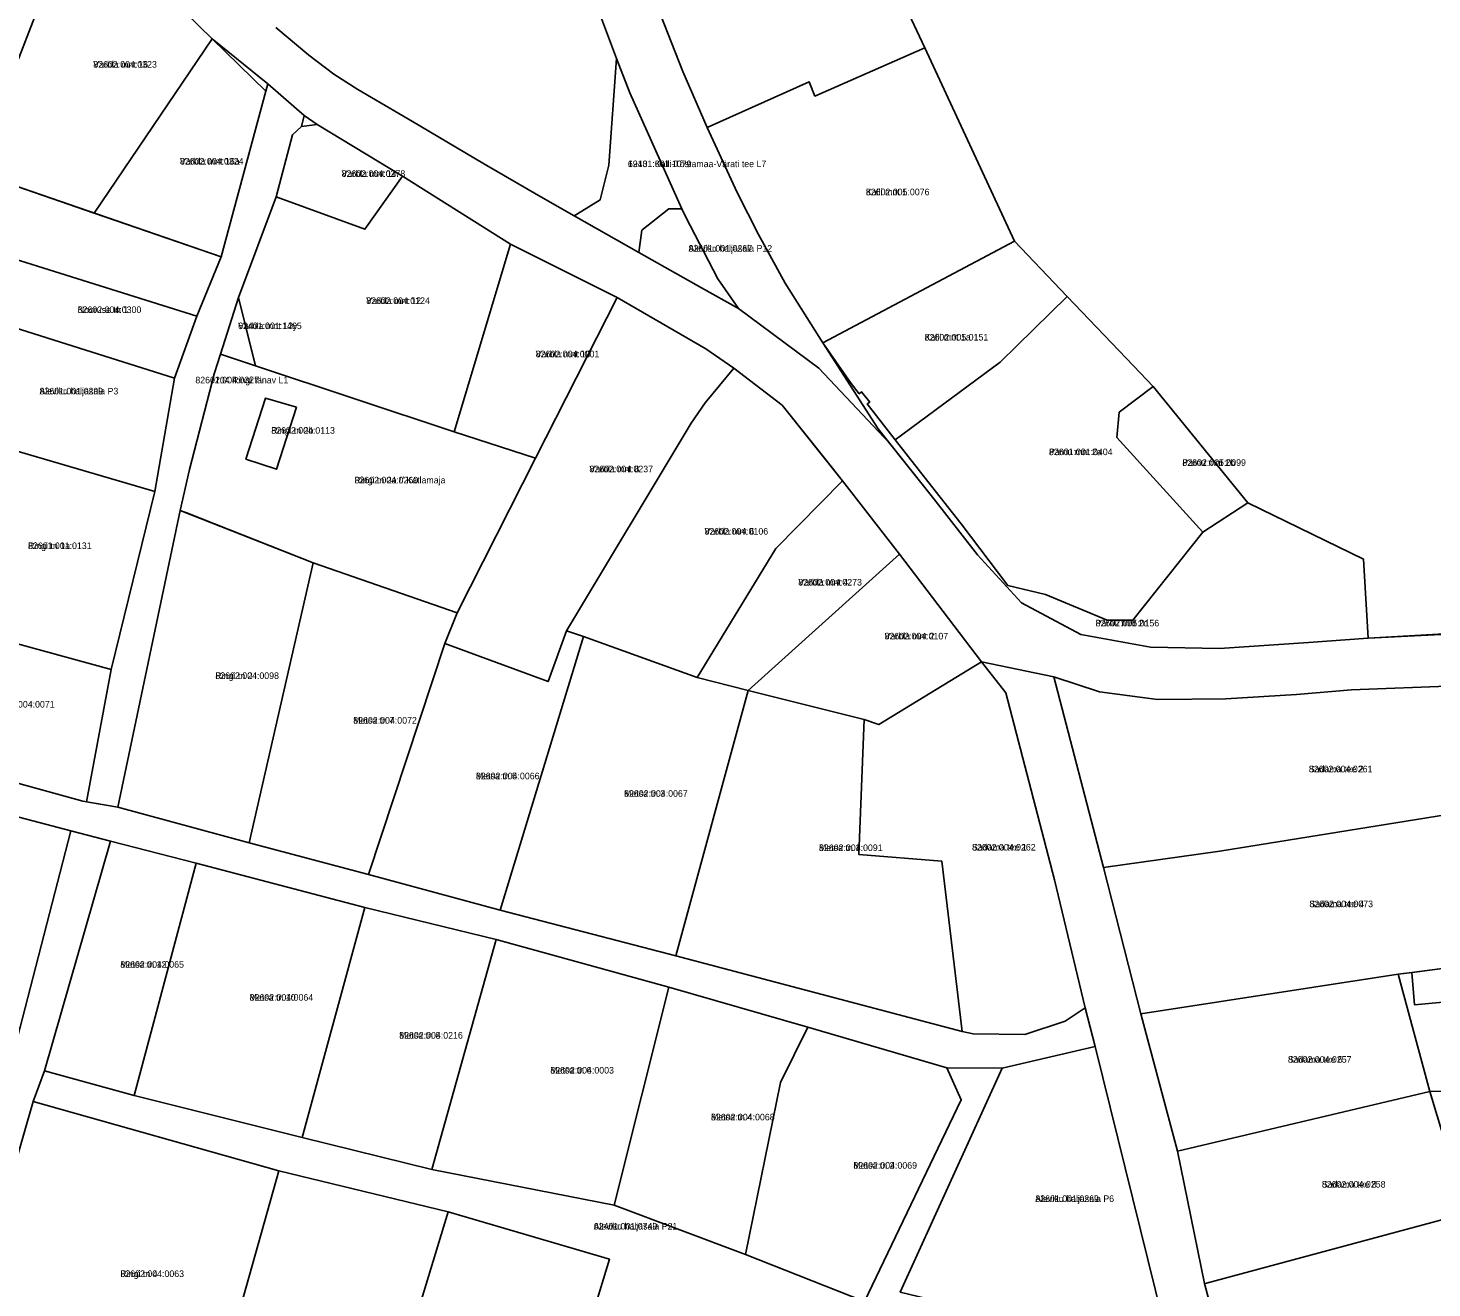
# Model space of a CAD drawing. Extents: x 491424 to 557740, y 6448618 to 6487207.
# Drawn here: x 499448.5 to 499768.6, y 6465851.5 to 6466138.8 of the extents above; entities that cross this region are included whole.
import ezdxf

# ---------------------------------------------------------------- set-up
doc = ezdxf.new("R2010")
doc.units = 0
for name, color, linetype in [('L_AADRESS', 7, 'Continuous'), ('PIIR', 7, 'Continuous'), ('TUNNUS', 7, 'Continuous')]:
    doc.layers.add(name, color=color, linetype=linetype)

msp = doc.modelspace()

# ---------------------------------------------------------------- linework, layer by layer
at = {"layer": 'PIIR'}
for points in [[(499579.95, 6466182.01), (499626.61, 6466190.35), (499652.93, 6466134.29), (499627.91, 6466123.27), (499626.61, 6466126.48), (499603.34, 6466116.11), (499597.78, 6466128.89), (499589.28, 6466150.63)], [(499407.26, 6466122.72), (499409.08, 6466128.35), (499426.33, 6466181.69), (499459.72, 6466166.41), (499436.29, 6466106), (499415.74, 6466117.84)], [(499490.51, 6466136.31), (499463.6, 6466096.59), (499436.29, 6466106), (499459.72, 6466166.41)], [(499502.73, 6466124.42), (499492.53, 6466086.63), (499463.6, 6466096.59), (499490.51, 6466136.31)], [(499603.34, 6466116.11), (499626.61, 6466126.48), (499627.91, 6466123.27), (499652.93, 6466134.29), (499673.44, 6466090.17), (499629.73, 6466067.03), (499621.13, 6466080.58), (499615.01, 6466091.72), (499610.15, 6466101.32)], [(499572.99, 6466095.95), (499573.8, 6466096.45), (499578.94, 6466099.6), (499580.89, 6466107.48), (499582.65, 6466131.85), (499585.72, 6466124.03), (499597.55, 6466097.53), (499594.57, 6466097.57), (499588.42, 6466092.68), (499587.73, 6466087.57)], [(499503.18, 6466126.09), (499511.5, 6466118.84), (499510.84, 6466116.31), (499508.83, 6466114.42), (499505.11, 6466100.26), (499496.47, 6466077.34), (499492.42, 6466064.45), (499491.07, 6466060.19), (499485.3, 6466038.14), (499483.2, 6466028.81), (499468.97, 6465961.11), (499461.84, 6465962.37), (499467.5, 6465992.52), (499477.45, 6466033.12), (499481.92, 6466058.94), (499487.01, 6466073.12), (499492.53, 6466086.63), (499502.73, 6466124.42)], [(499278.28, 6466026.77), (499288.17, 6466044.36), (499295.64, 6466056.89), (499304.55, 6466072.74), (499329.52, 6466088.43), (499340.09, 6466107.25), (499372.79, 6466096.28), (499404.99, 6466085.73), (499411.81, 6466106.27), (499415.74, 6466117.84), (499436.29, 6466106), (499492.53, 6466086.63), (499487.01, 6466073.12), (499437.57, 6466088.58), (499427.21, 6466088.67), (499423.61, 6466077.37), (499416.95, 6466056.51), (499375.43, 6466069.39), (499370.81, 6466055.84), (499368.18, 6466048.29), (499317.32, 6466066.39), (499311.41, 6466057.28), (499308.22, 6466047.25), (499283.94, 6466022.3)], [(499533.86, 6466105.03), (499525.34, 6466092.9), (499505.11, 6466100.26), (499508.83, 6466114.42), (499510.84, 6466116.31), (499514.47, 6466116.8)], [(499558.49, 6466089.53), (499545.7, 6466046.7), (499500.41, 6466061.78), (499496.47, 6466077.34), (499505.11, 6466100.26), (499525.34, 6466092.9), (499533.86, 6466105.03)], [(499610.46, 6466074.84), (499602.08, 6466079.52), (499587.73, 6466087.57), (499588.42, 6466092.68), (499594.57, 6466097.57), (499597.55, 6466097.53), (499598.38, 6466095.78), (499605.74, 6466081.59)], [(499487.01, 6466073.12), (499481.92, 6466058.94), (499423.61, 6466077.37), (499427.21, 6466088.67), (499437.57, 6466088.58)], [(499558.49, 6466089.53), (499582.81, 6466077.37), (499564.22, 6466040.7), (499545.7, 6466046.7)], [(499673.44, 6466090.17), (499685.4, 6466077.57), (499670.1, 6466062.57), (499646.22, 6466044.9), (499639.85, 6466053.07), (499640.39, 6466053.49), (499638.56, 6466055.82), (499638.01, 6466055.4), (499636.14, 6466057.76), (499629.73, 6466067.03)], [(499416.95, 6466056.51), (499423.61, 6466077.37), (499481.92, 6466058.94), (499477.45, 6466033.12), (499428.37, 6466047.47), (499429.97, 6466052.47)], [(499500.41, 6466061.78), (499492.42, 6466064.45), (499496.47, 6466077.34), (499499.81, 6466064.14)], [(499567.06, 6465989.79), (499543.54, 6465998.45), (499546.36, 6466005.46), (499564.22, 6466040.7), (499582.81, 6466077.37), (499603.04, 6466065.64), (499609.46, 6466061.24), (499602.9, 6466053.32), (499599.67, 6466048.69), (499571.28, 6466001.38)], [(499654.46, 6466034.36), (499646.22, 6466044.9), (499670.1, 6466062.57), (499685.4, 6466077.57), (499700.56, 6466061.8), (499705.05, 6466057.06), (499697.29, 6466051.19), (499696.72, 6466045.45), (499716.3, 6466023.87), (499700.36, 6466003.76), (499694.53, 6466003.76), (499680.49, 6466009.61), (499671.91, 6466011.67), (499661.24, 6466025.71)], [(499752.94, 6466017.7), (499754.05, 6465999.71), (499740.41, 6465998.68), (499720.16, 6465997.29), (499704.44, 6465997.59), (499688.52, 6466000.48), (499675, 6466007.7), (499664.94, 6466018.67), (499654.99, 6466031.48), (499642.3, 6466047.43), (499629.73, 6466067.03), (499636.14, 6466057.76), (499638.01, 6466055.4), (499638.56, 6466055.82), (499640.39, 6466053.49), (499639.85, 6466053.07), (499646.22, 6466044.9), (499654.46, 6466034.36), (499661.24, 6466025.71), (499671.91, 6466011.67), (499680.49, 6466009.61), (499694.53, 6466003.76), (499700.36, 6466003.76), (499716.3, 6466023.87), (499726.59, 6466030.54)], [(499564.22, 6466040.7), (499546.36, 6466005.46), (499513.5, 6466016.83), (499484.53, 6466028.29), (499483.2, 6466028.81), (499485.3, 6466038.14), (499491.07, 6466060.19), (499492.42, 6466064.45), (499500.41, 6466061.78), (499545.7, 6466046.7)], [(499575.14, 6466000.05), (499571.28, 6466001.38), (499599.67, 6466048.69), (499602.9, 6466053.32), (499609.46, 6466061.24), (499620.43, 6466052.83), (499630.19, 6466040.67), (499634.22, 6466035.55), (499619, 6466020.12), (499601.08, 6465990.74)], [(499705.05, 6466057.06), (499726.59, 6466030.54), (499716.3, 6466023.87), (499696.72, 6466045.45), (499697.29, 6466051.19)], [(499509.75, 6466052.36), (499505.15, 6466038.17), (499498.21, 6466040.51), (499502.65, 6466054.4)], [(499509.75, 6466052.36), (499502.65, 6466054.4), (499498.21, 6466040.51), (499505.15, 6466038.17)], [(499425.3, 6466038), (499428.37, 6466047.47), (499477.45, 6466033.12), (499467.5, 6465992.52), (499420.8, 6466005.32), (499420.94, 6466006.46)], [(499647.16, 6466018.82), (499612.68, 6465987.75), (499601.08, 6465990.74), (499619, 6466020.12), (499634.22, 6466035.55)], [(499483.2, 6466028.81), (499513.5, 6466016.83), (499498.97, 6465953.01), (499468.97, 6465961.11)], [(499665.85, 6465994.3), (499642.46, 6465979.96), (499639.13, 6465981.1), (499612.68, 6465987.75), (499647.16, 6466018.82)], [(499513.5, 6466016.83), (499546.36, 6466005.46), (499543.54, 6465998.45), (499526.12, 6465945.77), (499498.97, 6465953.01)], [(499411.95, 6465976.04), (499420.8, 6466005.32), (499467.5, 6465992.52), (499461.84, 6465962.37), (499461.04, 6465962.51)], [(499543.54, 6465998.45), (499567.06, 6465989.79), (499571.28, 6466001.38), (499575.14, 6466000.05), (499556.13, 6465937.67), (499526.12, 6465945.77)], [(499575.14, 6466000.05), (499601.08, 6465990.74), (499612.68, 6465987.75), (499596.22, 6465927.22), (499556.13, 6465937.67)], [(499639.13, 6465981.1), (499642.46, 6465979.96), (499665.85, 6465994.3), (499671.42, 6465987.21), (499682.5, 6465944.55), (499689.53, 6465915.38), (499684.92, 6465912.35), (499675.75, 6465909.33), (499663.96, 6465909.47), (499661.45, 6465909.97), (499656.82, 6465948.86), (499637.91, 6465950.36)], [(499682.36, 6465990.83), (499692.8, 6465987.47), (499706.02, 6465985.7), (499721.55, 6465985.81), (499737.7, 6465986.8), (499750.21, 6465987.91), (499774.03, 6465988.79), (499790.79, 6465987.93), (499795.92, 6465987.35), (499795.38, 6465983.96), (499791.96, 6465962.69), (499720.19, 6465951.11), (499693.66, 6465947.35)], [(499612.68, 6465987.75), (499639.13, 6465981.1), (499637.91, 6465950.36), (499656.82, 6465948.86), (499661.45, 6465909.97), (499596.22, 6465927.22)], [(499716.74, 6465852.52), (499717.16, 6465852.63), (499776.41, 6465868.6), (499768.06, 6465896.31), (499817.08, 6465896.71), (499823.35, 6465924.54), (499834.79, 6465922.31), (499871.35, 6465971.68), (499871.89, 6465972.41), (499884.79, 6465968.71), (499892.09, 6465966.48), (499891.86, 6465965.63), (499887.53, 6465949.17), (499886.14, 6465930.95), (499878.67, 6465916.45), (499870.44, 6465911.84), (499864.02, 6465866.23), (499857.4, 6465820.35), (499848.86, 6465820.4), (499846.67, 6465820.33), (499734.75, 6465821.09), (499724.98, 6465821.16), (499719.89, 6465840.63)], [(499409.42, 6465968.58), (499458.29, 6465955.73), (499446.68, 6465910.71), (499397.18, 6465926.22)], [(499720.19, 6465951.11), (499791.96, 6465962.69), (499788.37, 6465949.53), (499781.83, 6465925.68), (499773.23, 6465924.63), (499764.02, 6465923.46), (499760.87, 6465923.05), (499702.19, 6465913.99), (499693.66, 6465947.35)], [(499458.29, 6465955.73), (499467.34, 6465953.38), (499452.29, 6465901.06), (499449.67, 6465894.06), (499433.45, 6465837.68), (499438.47, 6465826.48), (499488.1, 6465815.52), (499525.32, 6465806.37), (499562.05, 6465795.59), (499585.26, 6465787.29), (499614.69, 6465779.12), (499606.44, 6465773.55), (499562.1, 6465786.17), (499562.54, 6465787.64), (499530.12, 6465796.73), (499529.52, 6465794.51), (499492.87, 6465804.94), (499450.85, 6465815.12), (499438.09, 6465817.92), (499422.13, 6465821.45), (499443.72, 6465899), (499446.68, 6465910.71)], [(499452.29, 6465901.06), (499467.34, 6465953.38), (499486.86, 6465948.41), (499472.73, 6465895.37)], [(499486.86, 6465948.41), (499525.34, 6465938.25), (499511.01, 6465885.86), (499472.73, 6465895.37)], [(499768.06, 6465896.31), (499760.87, 6465923.05), (499763.99, 6465923.46), (499764.62, 6465916.07), (499774.34, 6465916.99), (499773.23, 6465924.63), (499781.83, 6465925.68), (499788.37, 6465949.53), (499794.2, 6465948.12), (499818.66, 6465942.15), (499823.35, 6465924.54), (499817.08, 6465896.71)], [(499525.34, 6465938.25), (499555.28, 6465931), (499540.6, 6465878.53), (499511.01, 6465885.86)], [(499555.28, 6465931), (499594.57, 6465920.11), (499582.15, 6465870.38), (499540.6, 6465878.53)], [(499760.87, 6465923.05), (499768.06, 6465896.31), (499710.58, 6465882.72), (499702.19, 6465913.99)], [(499773.23, 6465924.63), (499774.34, 6465916.99), (499764.62, 6465916.07), (499763.99, 6465923.46)], [(499594.57, 6465920.11), (499626.29, 6465910.99), (499620.08, 6465898.36), (499612.12, 6465859.16), (499582.15, 6465870.38)], [(499620.08, 6465898.36), (499626.29, 6465910.99), (499657.96, 6465901.72), (499661.25, 6465894.43), (499639.23, 6465848.46), (499612.12, 6465859.16)], [(499691.8, 6465906.56), (499708.94, 6465837.09), (499674.22, 6465839.06), (499674.83, 6465843.95), (499647.36, 6465850.54), (499670.58, 6465901.67)], [(499452.29, 6465901.06), (499472.73, 6465895.37), (499511.01, 6465885.86), (499540.6, 6465878.53), (499582.15, 6465870.38), (499612.12, 6465859.16), (499639.23, 6465848.46), (499630.53, 6465828.65), (499599.86, 6465839.28), (499577.49, 6465846.35), (499581.06, 6465858.1), (499544.33, 6465868.88), (499505.73, 6465878.21), (499449.67, 6465894.06)], [(499768.06, 6465896.31), (499776.41, 6465868.6), (499717.16, 6465852.63), (499716.74, 6465852.52), (499710.58, 6465882.72)], [(499433.45, 6465837.68), (499449.67, 6465894.06), (499505.73, 6465878.21), (499488.1, 6465815.52), (499438.47, 6465826.48)], [(499505.73, 6465878.21), (499544.33, 6465868.88), (499525.32, 6465806.37), (499488.1, 6465815.52)], [(499544.33, 6465868.88), (499581.06, 6465858.1), (499577.49, 6465846.35), (499562.05, 6465795.59), (499525.32, 6465806.37)]]:
    msp.add_lwpolyline(points, close=True, dxfattribs=at)
for points in [[(499780.15, 6466148.46), (499866.41, 6466128.02), (499863.13, 6466078.7), (499858.28, 6466060.8), (499877.11, 6466046.77), (499886.78, 6466039.57), (499893.58, 6466028.81), (499893.13, 6466025.48), (499885.16, 6466029.07), (499838.8, 6466046.43), (499836.33, 6466036.93), (499801.98, 6466045.97), (499790.59, 6466030.06), (499788.73, 6466001.42), (499754.05, 6465999.71), (499752.94, 6466017.7), (499726.59, 6466030.54), (499705.05, 6466057.06), (499700.56, 6466061.8), (499685.4, 6466077.57), (499673.44, 6466090.17), (499652.93, 6466134.29), (499626.61, 6466190.35)], [(499774.03, 6465988.79), (499750.21, 6465987.91), (499737.7, 6465986.8), (499721.55, 6465985.81), (499706.02, 6465985.7), (499692.8, 6465987.47), (499682.36, 6465990.83), (499665.85, 6465994.3), (499647.16, 6466018.82), (499634.22, 6466035.55), (499620.43, 6466052.83), (499609.46, 6466061.24), (499603.04, 6466065.64), (499582.81, 6466077.37), (499558.49, 6466089.53), (499533.86, 6466105.03), (499514.47, 6466116.8), (499511.5, 6466118.84), (499503.18, 6466126.09), (499490.51, 6466136.31), (499459.72, 6466166.41)], [(499589.28, 6466150.63), (499597.78, 6466128.89), (499603.34, 6466116.11), (499610.15, 6466101.32), (499615.01, 6466091.72), (499621.13, 6466080.58), (499629.73, 6466067.03), (499642.3, 6466047.43), (499644.91, 6466044.14), (499628.81, 6466061.25), (499610.46, 6466074.84), (499605.74, 6466081.59), (499598.38, 6466095.78), (499597.55, 6466097.53), (499585.72, 6466124.03), (499582.65, 6466131.85), (499577.68, 6466145.26)], [(499577.68, 6466145.26), (499582.65, 6466131.85), (499580.89, 6466107.48), (499578.94, 6466099.6), (499573.8, 6466096.45), (499572.99, 6466095.95), (499564.89, 6466100.57), (499552.23, 6466107.96), (499536.17, 6466117.47), (499523.71, 6466124.79), (499518.21, 6466128.28), (499512.54, 6466132.6), (499505.05, 6466138.88)], [(499505.05, 6466138.88), (499512.54, 6466132.6), (499518.21, 6466128.28), (499523.71, 6466124.79), (499536.17, 6466117.47), (499552.23, 6466107.96), (499564.89, 6466100.57), (499572.99, 6466095.95), (499587.73, 6466087.57), (499602.08, 6466079.52), (499610.46, 6466074.84), (499628.81, 6466061.25), (499644.91, 6466044.14), (499654.99, 6466031.48), (499664.94, 6466018.67), (499675, 6466007.7), (499688.52, 6466000.48), (499704.44, 6465997.59), (499720.16, 6465997.29), (499740.41, 6465998.68), (499754.05, 6465999.71), (499774.01, 6466000.79)], [(499708.94, 6465837.09), (499691.8, 6465906.56), (499689.53, 6465915.38), (499682.5, 6465944.55), (499671.42, 6465987.21), (499665.85, 6465994.3), (499682.36, 6465990.83), (499693.66, 6465947.35), (499702.19, 6465913.99), (499710.58, 6465882.72), (499716.74, 6465852.52), (499719.89, 6465840.63)], [(499411.95, 6465976.04), (499461.04, 6465962.51), (499468.97, 6465961.11), (499498.97, 6465953.01), (499526.12, 6465945.77), (499556.13, 6465937.67), (499596.22, 6465927.22), (499661.45, 6465909.97), (499663.96, 6465909.47), (499675.75, 6465909.33), (499684.92, 6465912.35), (499689.53, 6465915.38), (499691.8, 6465906.56), (499670.58, 6465901.67), (499657.96, 6465901.72), (499626.29, 6465910.99), (499594.57, 6465920.11), (499555.28, 6465931), (499525.34, 6465938.25), (499486.86, 6465948.41), (499467.34, 6465953.38), (499458.29, 6465955.73), (499409.42, 6465968.58)], [(499639.23, 6465848.46), (499661.25, 6465894.43), (499657.96, 6465901.72), (499670.58, 6465901.67), (499647.36, 6465850.54)]]:
    msp.add_lwpolyline(points, dxfattribs=at)

# ---------------------------------------------------------------- texts
at = {"layer": 'L_AADRESS'}
for s, p in [('Varbla mnt 16', (499463.4, 6466129.74)), ('Varbla mnt 16a', (499483.16, 6466107.66)), ('19131 Kalli-Tõstamaa-Värati tee L7', (499585.27, 6466107.07)), ('Varbla mnt 14', (499520.02, 6466104.85)), ('Kalli mnt 1', (499639.52, 6466100.66)), ('Aleviku haljasala P12', (499599.09, 6466087.8)), ('Varbla mnt 12', (499525.63, 6466075.87)), ('Nooruse tn 1', (499459.85, 6466073.81)), ('Varbla mnt 12y', (499496.41, 6466070.14)), ('Kalli mnt 1a', (499652.92, 6466067.54)), ('Varbla mnt 10', (499564.26, 6466063.71)), ('Aleviku haljasala P3', (499451.15, 6466055.25)), ('8260104 Ringi tänav L1', (499486.67, 6466057.77)), ('Ringi tn 2b', (499503.98, 6466046.29)), ('Pärnu mnt 2a', (499681.26, 6466041.4)), ('Pärnu mnt 2b', (499711.66, 6466038.96)), ('Varbla mnt 8', (499576.5, 6466037.5)), ('Ringi tn 2a // Katlamaja', (499522.95, 6466034.96)), ('Varbla mnt 6', (499602.75, 6466023.29)), ('Ringi tn 1a', (499448.52, 6466019.99)), ('Varbla mnt 4', (499624.12, 6466011.68)), ('Pärnu mnt 2d', (499691.89, 6466002.36)), ('Varbla mnt 2', (499643.78, 6465999.39)), ('Ringi tn 2', (499491.23, 6465990.37)), ('Metsa tn 7', (499522.66, 6465980.18)), ('Sadama tee 2', (499740.5, 6465969.09)), ('Metsa tn 5', (499550.63, 6465967.5)), ('Metsa tn 3', (499584.41, 6465963.51)), ('Metsa tn 1', (499628.84, 6465951.14)), ('Sadama tee 1', (499663.72, 6465951.26)), ('Sadama tee 4', (499740.63, 6465938.34)), ('Metsa tn 12', (499469.57, 6465924.53)), ('Metsa tn 10', (499499.04, 6465917.02)), ('Metsa tn 8', (499533.14, 6465908.37)), ('Sadama tee 6', (499735.73, 6465902.88)), ('Metsa tn 6', (499567.59, 6465900.41)), ('Metsa tn 4', (499604.22, 6465889.73)), ('Metsa tn 2', (499636.68, 6465878.71)), ('Sadama tee 8', (499743.47, 6465874.41)), ('Aleviku haljasala P6', (499678.15, 6465871.13)), ('Aleviku haljasala P21', (499577.48, 6465864.85)), ('Ringi tn 4', (499469.59, 6465854.02))]:
    msp.add_text(s, height=1.5, dxfattribs=at).set_placement(p)
at = {"layer": 'TUNNUS'}
for s, p in [('82602:004:0323', (499463.4, 6466129.74)), ('82602:004:0324', (499483.16, 6466107.66)), ('62401:001:1079', (499585.27, 6466107.07)), ('82602:004:0278', (499520.02, 6466104.85)), ('82602:005:0076', (499639.52, 6466100.66)), ('82601:001:0267', (499599.09, 6466087.8)), ('82602:004:0124', (499525.63, 6466075.87)), ('82602:004:0300', (499459.85, 6466073.81)), ('62401:001:1465', (499496.41, 6466070.14)), ('82602:005:0151', (499652.92, 6466067.54)), ('82602:004:0001', (499564.26, 6466063.71)), ('82601:001:0299', (499451.15, 6466055.25)), ('82602:004:0327', (499486.67, 6466057.77)), ('82602:004:0113', (499503.98, 6466046.29)), ('82601:001:0404', (499681.26, 6466041.4)), ('82602:005:0099', (499711.66, 6466038.96)), ('82602:004:0237', (499576.5, 6466037.5)), ('82602:004:0260', (499522.95, 6466034.96)), ('82602:004:0106', (499602.75, 6466023.29)), ('82601:001:0131', (499448.52, 6466019.99)), ('82602:004:0273', (499624.12, 6466011.68)), ('82602:005:0156', (499691.89, 6466002.36)), ('82602:004:0107', (499643.78, 6465999.39)), ('82602:004:0098', (499491.23, 6465990.37)), ('82602:004:0071', (499440.09, 6465983.85)), ('82602:004:0072', (499522.66, 6465980.18)), ('82602:004:0261', (499740.5, 6465969.09)), ('82602:004:0066', (499550.63, 6465967.5)), ('82602:004:0067', (499584.41, 6465963.51)), ('82602:004:0091', (499628.84, 6465951.14)), ('82602:004:0262', (499663.72, 6465951.26)), ('82602:004:0073', (499740.63, 6465938.34)), ('82602:004:0065', (499469.57, 6465924.53)), ('82602:004:0064', (499499.04, 6465917.02)), ('82602:004:0216', (499533.14, 6465908.37)), ('82602:004:0257', (499735.73, 6465902.88)), ('82602:004:0003', (499567.59, 6465900.41)), ('82602:004:0068', (499604.22, 6465889.73)), ('82602:004:0069', (499636.68, 6465878.71)), ('82602:004:0258', (499743.47, 6465874.41)), ('82601:001:0269', (499678.15, 6465871.13)), ('62401:001:0749', (499577.48, 6465864.85)), ('82602:004:0063', (499469.59, 6465854.02))]:
    msp.add_text(s, height=1.5, dxfattribs=at).set_placement(p)

doc.saveas('drawing.dxf')
